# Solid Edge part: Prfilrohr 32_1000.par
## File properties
Username: ahadarics
Dokumentum tartalom típus: 0
Author: ahadarics
Last saved by: ahadarics
Revision: 93
Sűrűség: 0,000 kg/m^3
Pontosság: 0,990
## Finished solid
Body 1: solid body, 179 faces, 531 edges, 354 vertices.
  Faces by surface: cylinder 109, plane 70
  Edges by curve: line 313, circle 218
Bounding box of the edges (mm): 44.254 x 44.254 x 1041.000, from (-22.1268, -22.1268, -13) to (22.1268, 22.1268, 1028).
Cylindrical faces by radius (mm): R0.1 x16, R0.2 x30, R0.5 x32, R1 x6, R2.7 x8, R4.5 x4, R4.7 x4, R16 x1, R18 x8
Planar faces by outward normal: +x 6, +y 6, +z 1, -x 4, -y 4, -z 1, oblique 48
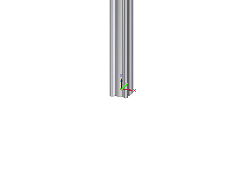
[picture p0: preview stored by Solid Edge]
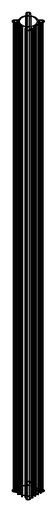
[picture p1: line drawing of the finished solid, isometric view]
